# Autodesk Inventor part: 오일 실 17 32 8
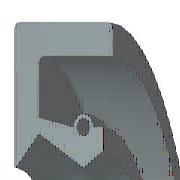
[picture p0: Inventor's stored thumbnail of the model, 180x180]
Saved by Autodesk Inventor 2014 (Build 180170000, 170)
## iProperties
IsCustomPart: 1
Created: 2012-02
Part Number: 오일 실 17 32 8
Material: 고무
Description: 오일-실
Document SubType Name: Modeling
Standard: KS B 2804
Designer: mduedu
Standards Organization: KS
Language: ko-KR
Size Designation: D - 17 32 8
Categories: <MemberInstance><Categories><Category DisplayName="샤프트 부품" InternalName="7f7aeb1f-a693-4053-b835-cee3144e0d98" Mnemonic="SHFT"><Category DisplayName="실링" Intern
Density: 0.93 g/cm^3
Appearance: 고무 - 검은색 - 버전 1.1
Author: mduedu
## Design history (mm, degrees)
revolve "본체" stored, may be unused: angle "d17" = 90 deg
revolve "스프링1" stored, may be unused: angle "d18" = 90 deg
body "Solid1"
sketch "스케치1"
  geometry: L1 (0, 16)-(8, 16); L2 (8, 14.25)-(1.75, 14.25); L3 (1.75, 10.25)-(4.9, 8.5); L4 (4.9, 8.5)-(0, 8.5); L5 (0, 0)-(9.586, 0) reference; L6 (4.9, 8.5)-(6.3, 9.375); L7 (0, 18)-(0, -3) reference; L8 (-1.941, 0)-(11.507, 0) reference; L9 (4.2, 10.6)-(1.75, 11.21); L10 (1.75, 11.21)-(1.75, 14.25); L11 (0, 16)-(0, 8.588); L12 (4.9, 8.5)-(0, 8.5); L13 (1.75, 10.25)-(0.152, 8.528); L14 (8, 16)-(8, 14.25); L15 (5.6, 10.6)-(6.3, 10.6); L16 (6.3, 10.6)-(6.3, 9.375); C1 r 0.455 at (4.9, 10.6); A1 r 0.7 centre (4.9, 10.6) between (5.6, 10.6) and (4.2, 10.6); A2 r 0.088 centre (0.088, 8.588) between (0, 8.588) and (0.152, 8.528); 1 further point
  constraints: 28 end point, 5 horizontal alignment, 5 point on line, 4 point on circle, 4 vertical alignment, 3 centre point, 3 tangent, 2 collinear, 2 horizontal, 2 perpendicular, 1 coincident, 1 parallel
  dimensions: "d0" = 32 diameter of L1 L5 (= SD2); "d1" = 1.75 distance of L1.end L2.start (= SD); "d2" = 0.91 diameter of C1 (= SPDI); "d3" = 1.4 diameter of A1 (= SPDA); "d4" = 17 diameter of L3.end L5 (= NND); "d5" = 20.5 diameter of L3.start L5 (= TKDM); "d7" = 22.42 diameter of L9.end L5 (= TKDM + 0.24 x SWDT); "d8" = 1.75 distance between parallel lines of L11 L10 (= SD); "d9" = 4.9 distance from line of L11 C1.centre (= SPDST); "d10" = 21.2 diameter of C1.centre L5 (= HLDM); "d11" = 0.0875 radius of A2 (= 0.25 x LAB); "d12" = 6.3 distance between parallel lines of L11 L16 (= SDI); "d13" = 18.75 diameter of L6.end L5 (= ABDM); "d14" = 8 distance from line of L11 L1.end (= SWDT)
fillet "모깎기1" dims "d6" = 0.3 (= RR)
other parameters: "SD2" = 32 [user parameter; used in 1 equation term], "SWDT" = 8 [user parameter; used in 2 equation terms], "RR" = 0.3 [user parameter; used in 1 equation term], "SD" = 1.75 [user parameter; used in 2 equation terms], "NND" = 17 [user parameter; used in 1 equation term], "SPDA" = 1.4 [user parameter; used in 1 equation term], "SPDI" = 0.91 [user parameter; used in 1 equation term], "TKDM" = 20.5 [user parameter; used in 2 equation terms], "HLDM" = 21.2 [user parameter; used in 1 equation term], "ABDM" = 18.75 [user parameter; used in 1 equation term], "SDI" = 6.3 [user parameter; used in 1 equation term], "SPDST" = 4.9 [user parameter; used in 1 equation term], "LAB" = 0.35 [user parameter; used in 1 equation term], "d15" = 0, "d16" = 0, "d19" = 0
